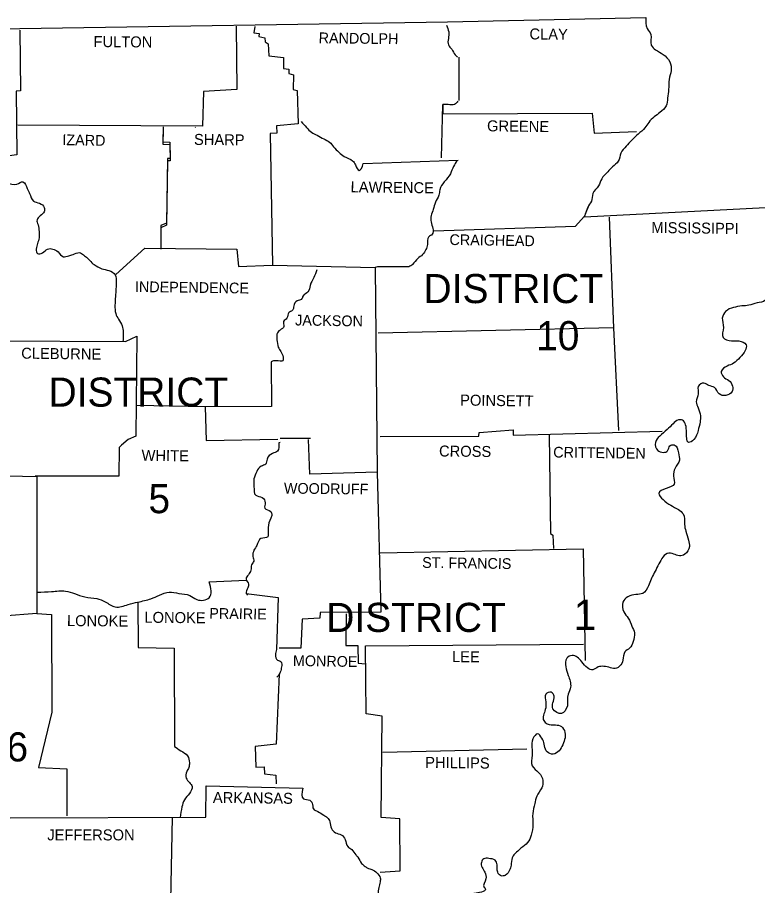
# Model space of a CAD drawing. Extents: x -33639 to 34530, y -17264 to 5867.
# Drawn here: x -16002 to -14408, y -9004 to -7133 of the extents above; entities that cross this region are included whole.
import ezdxf

# ---------------------------------------------------------------- set-up
doc = ezdxf.new("R2010")
doc.units = 0
for name, color, linetype in [('1', 7, 'Continuous'), ('2', 7, 'Continuous'), ('3', 7, 'Continuous'), ('S_MISC_BOUNDARY', 7, 'Continuous')]:
    doc.layers.add(name, color=color, linetype=linetype)

msp = doc.modelspace()

# ---------------------------------------------------------------- linework, layer by layer
at = {"layer": '1'}
for p, q in [((-14780.6, -7563.1), (-14774, -7542.7)), ((-14779, -7556.5), (-14772.4, -7540.5)), ((-15436.7, -8039.7), (-15371.2, -8039.7))]:
    msp.add_line(p, q, dxfattribs=at)
for points in [[(-17667.8, -7158.5), (-16777.9, -7159.1), (-15996.9, -7157.4), (-15075.6, -7143.1), (-14648.6, -7133.2)], [(-15996.9, -7160.7), (-15995.8, -7291.7), (-16005.2, -7292.3), (-16003.5, -7429.3), (-16042.1, -7434.8), (-16038.8, -7471.7), (-16025.5, -7488.8), (-16026.6, -7532.2), (-16101.5, -7535), (-16104.2, -7602.1), (-16172.5, -7604.3), (-16175.8, -7685.8), (-16171.9, -7692.4), (-16170.3, -7822.3), (-16052.5, -7830), (-16054.2, -8120), (-15960.6, -8122.8), (-15960.6, -8417.8), (-16034.4, -8423.3), (-16039.9, -8488.2), (-16163.7, -8488.8)], [(-15530.8, -7152.5), (-15529.7, -7289), (-15601.2, -7292.8), (-15603.4, -7367.7), (-16001.3, -7365.5)], [(-15491.2, -7153), (-15492.8, -7166.3), (-15481.8, -7167.9), (-15482.3, -7174.5), (-15469.7, -7177.3), (-15468.6, -7186.1), (-15462.5, -7189.9), (-15460.9, -7216.3), (-15429.5, -7219.6), (-15429.5, -7243.3), (-15418, -7245), (-15418, -7254.3), (-15408, -7257.1), (-15408.6, -7289), (-15399.8, -7290.6), (-15397.6, -7362.7), (-15444.4, -7367.1), (-15443.8, -7382.5), (-15458.1, -7383.1), (-15453.2, -7667.1), (-15231.4, -7672), (-15227.5, -8113.4), (-15372.3, -8117.3), (-15375, -8043)], [(-15051.4, -7219.1), (-15051.4, -7312.1)], [(-15088.8, -7435.9), (-15086.1, -7320.9), (-15086.1, -7341.3), (-14764.1, -7339.6), (-14759.7, -7382.5), (-14668.9, -7379.2)], [(-15688.2, -7369.3), (-15689.3, -7401.3), (-15673.9, -7402.4), (-15673.3, -7437.6), (-15678.8, -7437.6), (-15681, -7576.3), (-15693.7, -7581.8), (-15693.7, -7628)], [(-15619.4, -7370.4), (-15618.8, -7369.9)], [(-15688.2, -7374.3), (-15689.3, -7406.2), (-15673.9, -7407.3), (-15673.3, -7442.5), (-15678.8, -7442.5), (-15681, -7581.2), (-15693.7, -7586.7), (-15693.7, -7633)], [(-15257.3, -7448), (-15053.1, -7440.9)], [(-14780.6, -7563.1), (-14362.9, -7541.6)], [(-15105.4, -7593.3), (-14799.9, -7583.4), (-14781.7, -7562.5)], [(-14727.8, -7563.6), (-14718.5, -7801.9), (-14707.4, -8023.7)], [(-15790.5, -7686.9), (-15727.8, -7630.2), (-15529.7, -7633), (-15525.8, -7669.8), (-15453.7, -7667.1)], [(-15159.3, -7670.9), (-15226.4, -7670.9), (-15231.4, -7672)], [(-14718.5, -7801.9), (-15225.3, -7813.5)], [(-16052.5, -7830), (-15769.6, -7831.6), (-15745.4, -7820.1), (-15747.1, -8035.3), (-15763.6, -8042.4), (-15778.4, -8055.1), (-15783.4, -8060), (-15783.9, -8121.7), (-15963.9, -8121.7)], [(-15455.9, -7875.1), (-15454.8, -7972), (-15597.9, -7972.5), (-15744.9, -7969.8)], [(-15597.9, -7972.5), (-15595.7, -8044.6), (-15441.1, -8041.9)], [(-15220.9, -8036.4), (-15008.5, -8035.3), (-15007.9, -8027.6), (-14934.2, -8022.1), (-14934.2, -8033.6), (-14613.9, -8024.8)], [(-14857.1, -8033.6), (-14854.4, -8245.5), (-14849.4, -8248.8), (-14847.8, -8277.4)], [(-15436.7, -8049), (-15439.4, -8049.6)], [(-15227.5, -8113.4), (-15219.3, -8415), (-15350.3, -8415.6), (-15350.8, -8427.7), (-15388.8, -8429.9), (-15392.1, -8492.6), (-15438.3, -8492.6)], [(-15220.9, -8286.8), (-14783.9, -8278)], [(-14783.9, -8278), (-14779.5, -8519)], [(-15589.1, -8349.5), (-15509.3, -8345.7)], [(-15509.3, -8374.3), (-15440.5, -8383.1), (-15444.4, -8495.4)], [(-15743.2, -8392.4), (-15742.1, -8491), (-15664.5, -8492.6), (-15664, -8703.9)], [(-15960.6, -8417.8), (-15928.7, -8420), (-15928.1, -8630.2), (-15956.8, -8749.6), (-15895.7, -8752.4), (-15896.2, -8853.6)], [(-15294.1, -8418.3), (-15294.7, -8486.6), (-15269.4, -8486.6), (-15268.3, -8524.5), (-15252.3, -8526.2)], [(-15220.9, -8974.7), (-15178, -8972), (-15178.6, -8860.2), (-15218.7, -8857.5), (-15216.5, -8639), (-15251.2, -8634), (-15252.3, -8487.1), (-14782.8, -8483.8)], [(-15438.3, -8548.2), (-15444.9, -8699), (-15490.1, -8703.9), (-15489, -8748.5), (-15470.8, -8748), (-15470.2, -8763.4), (-15445.5, -8766.1), (-15444.9, -8784.3)], [(-15215.4, -8716.6), (-14905, -8708.9)], [(-15668.9, -8856.7), (-15673.3, -9072.7), (-15596.8, -9078.7)]]:
    msp.add_lwpolyline(points, dxfattribs=at)
for points in [[(-14648.6, -7133.2), (-14645.8, -7157.4), (-14638.1, -7170.1), (-14637, -7193.2), (-14627.6, -7203.1), (-14611.7, -7213), (-14597.4, -7229), (-14594.1, -7247.7), (-14598.5, -7267), (-14599.6, -7288.4), (-14601.8, -7307.1), (-14605.1, -7324.2), (-14618.3, -7338), (-14630.9, -7347.9), (-14642.5, -7359.4), (-14650.8, -7371.5), (-14665.1, -7384.7), (-14679.4, -7398.5), (-14690.9, -7410.6), (-14702.5, -7426), (-14708, -7443.1), (-14720.7, -7455.2), (-14730.6, -7466.2), (-14743.8, -7481.1), (-14750.4, -7495.9), (-14763, -7513), (-14765.8, -7529.5), (-14774, -7542.7), (-14774.6, -7544.9)], [(-15078.4, -7150.3), (-15073.4, -7164.1), (-15074, -7178.9), (-15074, -7192.7), (-15066.8, -7202), (-15059.7, -7213.6), (-15054.2, -7218.5)], [(-15053.6, -7313.7), (-15060.8, -7320.9), (-15074.5, -7320.9), (-15086.1, -7320.9)], [(-15391.5, -7357.8), (-15379.4, -7370.4), (-15369, -7380.9), (-15356.9, -7386.9), (-15342.6, -7395.2), (-15329.9, -7401.8), (-15321.6, -7412.3), (-15310.1, -7423.8), (-15298.5, -7433.2), (-15280.4, -7442), (-15274.3, -7451.3), (-15266.1, -7462.9), (-15257.3, -7448)], [(-15054.7, -7441.4), (-15063, -7454.6), (-15069.6, -7470), (-15082.8, -7487.7), (-15092.7, -7504.7), (-15094.3, -7516.3), (-15102.1, -7531.7), (-15106.5, -7547.1), (-15111.4, -7560.3), (-15111.4, -7574.1), (-15107.6, -7587.8), (-15108.7, -7600.5), (-15116.9, -7606.5), (-15119.1, -7622.5), (-15122.4, -7633.5), (-15129.6, -7644.5), (-15140, -7652.8), (-15151, -7665.4), (-15159.3, -7670.9)], [(-16025.5, -7488.8), (-16003.5, -7492.6), (-15990.3, -7487.7), (-15981, -7502), (-15976, -7513), (-15967.8, -7528.9), (-15954.6, -7533.9), (-15944.6, -7542.7), (-15944.6, -7552.1), (-15953.4, -7560.9), (-15960.1, -7569.7), (-15957.9, -7580.1), (-15955.7, -7594.4), (-15955.7, -7608.2), (-15959, -7620.8), (-15961.7, -7632.4), (-15959, -7642.3), (-15948.5, -7640.7), (-15937.5, -7632.4), (-15925.9, -7632.4), (-15914.9, -7638.5), (-15903.4, -7648.9), (-15891.8, -7646.7), (-15882.5, -7644), (-15869.2, -7640.1), (-15859.9, -7645.1), (-15851.6, -7651.7), (-15841.7, -7662.1), (-15832.4, -7668.7), (-15820.3, -7674.8), (-15805.4, -7678.6), (-15791.6, -7688), (-15789.4, -7703.9), (-15790, -7717.7), (-15791.1, -7734.8), (-15792.2, -7753.5), (-15790.5, -7771.6), (-15784.5, -7783.8), (-15776.8, -7798.1), (-15774.6, -7811.3), (-15775.1, -7832.2)], [(-14369, -7542.1), (-14362.9, -7541.6), (-14344.2, -7561.4), (-14336, -7577.9), (-14323.9, -7587.3), (-14310.1, -7592.2), (-14299.6, -7604.9), (-14292.5, -7618.6), (-14296.3, -7630.8), (-14311.7, -7631.9), (-14328.8, -7634.6), (-14345.3, -7634.1), (-14358.5, -7645.1), (-14346.4, -7659.9), (-14330.5, -7673.7), (-14326.1, -7688.5), (-14334.9, -7702.8), (-14352.5, -7710.6), (-14369.5, -7717.2), (-14384.9, -7730.4), (-14392.1, -7743), (-14409.2, -7748.5), (-14426.8, -7753.5), (-14442.2, -7755.1), (-14459.8, -7758.4), (-14476.9, -7766.7), (-14484, -7781), (-14481.8, -7801.4), (-14482.4, -7822.8), (-14464.2, -7830), (-14448.2, -7830.5), (-14432.8, -7838.8), (-14434.5, -7850.9), (-14446, -7866.3), (-14459.8, -7878.4), (-14473.5, -7884.5), (-14486.2, -7896), (-14481.8, -7907.6), (-14470.2, -7915.3), (-14462, -7927.9), (-14463.1, -7939.5), (-14476.3, -7947.8), (-14490.6, -7944.5), (-14501.1, -7930.7), (-14513.2, -7926.3), (-14523.6, -7921.3), (-14535.7, -7928.5), (-14535.7, -7944.5), (-14540.1, -7961.5), (-14536.3, -7974.2), (-14531.3, -7991.8), (-14531.9, -8005), (-14536.3, -8023.7), (-14545.6, -8043), (-14556.7, -8049), (-14561.1, -8028.1), (-14563.3, -8011), (-14569.9, -8001.1), (-14578.7, -8000.6), (-14590.2, -8008.8), (-14602.9, -8021.5), (-14618.8, -8035.3), (-14628.2, -8049), (-14623.2, -8066.1), (-14611.1, -8070.5), (-14601.8, -8067.2), (-14596.8, -8056.2), (-14587.5, -8054.5), (-14578.7, -8071.6)], [(-15357.4, -7677), (-15364, -7694), (-15371.7, -7710.6), (-15376.7, -7724.9), (-15387.1, -7733.1), (-15390.4, -7740.8), (-15399.8, -7744.1), (-15406.9, -7755.1), (-15410.3, -7765), (-15418, -7769.4), (-15421.8, -7781.5), (-15429, -7788.2), (-15428.4, -7799.2), (-15436.7, -7806.9), (-15443.3, -7815.7), (-15443.3, -7827.8), (-15440.5, -7843.7), (-15435, -7853.1), (-15430.1, -7865.2), (-15430.6, -7872.9), (-15444.4, -7872.9), (-15455.9, -7875.1)], [(-15439.4, -8049.6), (-15442.2, -8067.7), (-15452.6, -8072.7), (-15464.7, -8084.8), (-15467.5, -8095.8), (-15477.4, -8100.2), (-15486.7, -8111.8), (-15492.8, -8127.7), (-15492.8, -8144.2), (-15489, -8162.9), (-15475.2, -8167.9), (-15468.6, -8178.9), (-15469.7, -8190.5), (-15456.5, -8198.2), (-15454.3, -8204.8), (-15456.5, -8211.9), (-15462.5, -8232.3), (-15462, -8246), (-15463.1, -8252.1), (-15477.9, -8256), (-15486.7, -8270.8), (-15492.8, -8281.3), (-15495, -8295), (-15493.4, -8304.9), (-15497.8, -8312.6), (-15499.4, -8324.2), (-15504.9, -8334.1), (-15509.9, -8343.5), (-15504.4, -8354.5), (-15506, -8362.2), (-15509.3, -8374.3), (-15506.6, -8378.1)], [(-14578.7, -8071.6), (-14576.5, -8087.5), (-14585.8, -8104.6), (-14589.1, -8121.7), (-14587.5, -8138.7), (-14605.1, -8148.1), (-14620.5, -8159.1), (-14611.7, -8172.3), (-14595.2, -8184.4), (-14578.7, -8193.8), (-14568.2, -8203.1), (-14565.5, -8225.7), (-14562.7, -8240), (-14557.2, -8259.8), (-14555, -8273.6), (-14564.9, -8290.1), (-14576.5, -8293.4), (-14588.6, -8289.5), (-14602.9, -8288.4), (-14614.4, -8299.4), (-14622.7, -8314.8), (-14630.9, -8330.3), (-14637, -8343.5), (-14643.1, -8357.8), (-14655.2, -8374.3), (-14670, -8377), (-14687.6, -8381.4), (-14698.1, -8393.5), (-14696.4, -8413.9), (-14686.5, -8427.7), (-14678.8, -8444.7), (-14673.3, -8459.6), (-14676.1, -8478.3), (-14683.8, -8492.1), (-14693.7, -8500.3), (-14698.1, -8517.9), (-14705.2, -8531.1), (-14711.9, -8535.5), (-14725.1, -8534.4), (-14739.4, -8531.7), (-14751.5, -8532.8), (-14763, -8538.8), (-14774.6, -8535), (-14786.7, -8521.8), (-14796.6, -8511.9), (-14807.6, -8508), (-14819.2, -8514.1), (-14821.4, -8532.2), (-14815.9, -8550.9), (-14810.9, -8576.3), (-14815.9, -8591.7), (-14817.5, -8617)], [(-15959.5, -8371.5), (-15928.7, -8370.4), (-15898.4, -8369.3), (-15879.2, -8374.8), (-15857.1, -8382), (-15831.3, -8385.3), (-15813.1, -8392.4), (-15791.6, -8403.4), (-15764.1, -8398.5), (-15742.7, -8393), (-15714.6, -8385.8), (-15696.4, -8378.1), (-15675.5, -8371.5), (-15654.6, -8374.3), (-15630.9, -8378.7), (-15616.1, -8387.5), (-15589.1, -8383.6), (-15589.1, -8349.5)], [(-15444.4, -8495.4), (-15446.6, -8506.4), (-15442.2, -8517.9), (-15434.5, -8521.8), (-15433.4, -8532.8), (-15436.1, -8543.8), (-15438.3, -8548.2), (-15443.3, -8554.8)], [(-14817.5, -8617), (-14830.2, -8632.9), (-14848.9, -8623), (-14848.9, -8609.8), (-14846.1, -8596.1), (-14852.7, -8587.3), (-14864.3, -8591.1), (-14864.3, -8608.2), (-14865.4, -8624.7), (-14868.7, -8648.4), (-14861, -8655.5), (-14843.4, -8657.7), (-14830.7, -8661), (-14823, -8673.7), (-14823.6, -8689.1), (-14829.6, -8703.9), (-14838.4, -8716), (-14852.2, -8720.5), (-14863.2, -8713.3), (-14867.6, -8699), (-14872.6, -8686.3), (-14881.9, -8677), (-14891.8, -8687.4), (-14894, -8706.7), (-14893.5, -8723.2), (-14893.5, -8745.8), (-14879.2, -8760.6), (-14870.4, -8777.7), (-14873.1, -8793.1), (-14883.6, -8811.3), (-14888, -8827.2), (-14892.4, -8848.7), (-14891.8, -8872.3), (-14895.7, -8895.5), (-14903.4, -8910.9), (-14917.7, -8923.5), (-14927, -8931.8), (-14934.7, -8940), (-14938.6, -8956.6), (-14941.3, -8968.1), (-14951.8, -8981.9), (-14960.1, -8983), (-14966.7, -8977.5), (-14968.9, -8968.1), (-14968.9, -8958.8), (-14973.3, -8949.4), (-14987, -8945.5), (-14998, -8946.1), (-15003, -8953.8), (-14995.8, -8975.3), (-14993.1, -8989), (-14996.9, -9007.7), (-14994.7, -9009.9), (-15014.5, -9020.4), (-15030.5, -9022), (-15043.7, -9025.9), (-15056.4, -9034.2), (-15062.4, -9046.3), (-15071.2, -9056.2), (-15078.9, -9065.5), (-15089.4, -9069.9), (-15101, -9067.7), (-15116.4, -9066.1), (-15125.2, -9077.1), (-15122.4, -9093), (-15112, -9102.4), (-15096.5, -9106.8), (-15080.6, -9105.7), (-15065.2, -9104), (-15050.9, -9111.8), (-15053.6, -9126.6), (-15067.4, -9133.8), (-15087.7, -9136), (-15104.3, -9134.3), (-15124.1, -9138.7), (-15134, -9151.4), (-15128.5, -9170.6), (-15107, -9178.3), (-15097.1, -9196.5), (-15096.5, -9213.6), (-15103.7, -9236.1), (-15113.6, -9246.6), (-15132.9, -9251), (-15147.7, -9253.7), (-15149.9, -9279.1), (-15156.5, -9291.7), (-15168.1, -9295.6), (-15184.6, -9287.3), (-15194.5, -9283.5), (-15206.6, -9278), (-15222, -9268.6), (-15233.6, -9270.3), (-15230.3, -9294.5), (-15229.2, -9295.6), (-15216, -9313.7), (-15202.8, -9328), (-15196.7, -9345.1)], [(-15664, -8703.9), (-15650.2, -8713.3), (-15635.9, -8724.3), (-15632, -8739.2), (-15633.1, -8749.6), (-15637.5, -8758.4), (-15638.6, -8772.2), (-15632, -8782.1), (-15626, -8790.3), (-15632, -8805.2), (-15642.5, -8819), (-15648, -8834.4), (-15651.9, -8857.5)]]:
    msp.add_spline(points, degree=3, dxfattribs=at)
at = {"layer": 'S_MISC_BOUNDARY'}
msp.add_lwpolyline([(-16017.8, -8858), (-15596.8, -8856.4), (-15595.7, -8788.7), (-15387.7, -8794.2)], dxfattribs=at)
msp.add_spline([(-15387.7, -8794.2), (-15386, -8816.8), (-15372.8, -8820.1), (-15367.3, -8826.1), (-15364.6, -8838.8), (-15355.2, -8844.3), (-15342.6, -8852), (-15334.9, -8857.5), (-15329.3, -8866.3), (-15326, -8880.6), (-15317.2, -8890), (-15305.1, -8894.4), (-15296.3, -8904.8), (-15290.8, -8919.7), (-15282, -8926.3), (-15273.2, -8937.8), (-15268.8, -8942.8), (-15261.1, -8956), (-15253.4, -8962.6), (-15247.9, -8966.5), (-15239.1, -8969.2), (-15228.1, -8976.4), (-15220.9, -8987.4), (-15220.9, -8995.6), (-15223.7, -9008.3), (-15225.9, -9021.5), (-15227, -9036.4), (-15228.1, -9049.6), (-15223.1, -9060.6), (-15225.9, -9077.1), (-15231.4, -9085.9), (-15231.9, -9098), (-15233.6, -9116.2), (-15235.8, -9126.6), (-15240.7, -9143.7), (-15247.9, -9152.5)], degree=3, dxfattribs=at)

# ---------------------------------------------------------------- texts
at = {"layer": '1'}
msp.add_text('1', height=66, dxfattribs=at).set_placement((-14804.3, -8453.5))
at = {"layer": '2'}
for s, height, rotation, p in [('CLAY', 23.66, 359.2258, (-14899.5, -7180.6)), ('FULTON', 23.66, 359.4996, (-15838.4, -7197.1)), ('RANDOLPH', 23.11, 359.2583, (-15353.6, -7188.8)), ('GREENE', 23.67, 359.2361, (-14990.9, -7378.7)), ('IZARD', 23.11, 358.9258, (-15905.6, -7408.4)), ('SHARP', 23.66, 359.3905, (-15622.1, -7407.9)), ('LAWRENCE', 23.67, 359.2678, (-15284.8, -7510.2)), ('MISSISSIPPI', 23.66, 359.3097, (-14637, -7597.7)), ('CRAIGHEAD', 23.11, 359.1159, (-15071.8, -7623.6)), ('INDEPENDENCE', 23.108, 359.2187, (-15749.3, -7724.9)), ('JACKSON', 23.11, 359.1352, (-15404.2, -7797)), ('CLEBURNE', 23.66, 359.2535, (-15994.2, -7868.5)), ('POINSETT', 23.66, 359.1987, (-15048.8, -7969.5)), ('CROSS', 23.66, 359.3839, (-15094.3, -8079.3)), ('CRITTENDEN', 23.11, 359.213, (-14848.3, -8081.5)), ('WHITE', 23.67, 359.3139, (-15735, -8088.6)), ('WOODRUFF', 23.11, 359.2748, (-15428.4, -8159.1)), ('ST. FRANCIS', 23.108, 359.2216, (-15130.7, -8319.2)), ('LONOKE', 23.67, 359.4974, (-15728.9, -8437.6)), ('PRAIRIE', 23.11, 359.2116, (-15589.1, -8428.8)), ('LONOKE', 23.67, 359.4974, (-15895.7, -8444.7)), ('MONROE', 23.11, 359.0331, (-15409.1, -8530.6)), ('LEE', 23.67, 359.4327, (-15066.3, -8522.3)), ('PHILLIPS', 23.66, 359.3179, (-15124.1, -8750.2)), ('ARKANSAS', 23.66, 359.2678, (-15581.4, -8825.6))]:
    msp.add_text(s, height=height, rotation=rotation, dxfattribs=at).set_placement(p)
msp.add_text('JEFFERSON', height=23.67, dxfattribs=at).set_placement((-15938, -8906.5))
at = {"layer": '3'}
for s, height, p in [('DISTRICT', 62.74, (-15127.6, -7748.9)), ('10', 62.74, (-14885.1, -7850.4)), ('DISTRICT', 62.74, (-15935.3, -7972)), ('5', 62.7, (-15720.1, -8201.5)), ('DISTRICT', 62.74, (-15337.1, -8457.4)), ('DISTRICT 6', 62.74, (-16436.1, -8736.4))]:
    msp.add_text(s, height=height, dxfattribs=at).set_placement(p)

doc.saveas('drawing.dxf')
